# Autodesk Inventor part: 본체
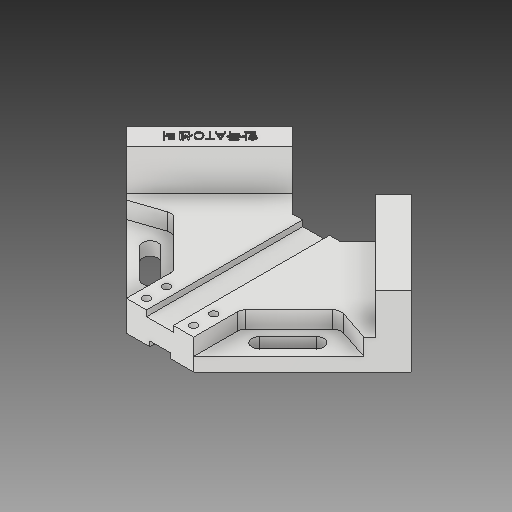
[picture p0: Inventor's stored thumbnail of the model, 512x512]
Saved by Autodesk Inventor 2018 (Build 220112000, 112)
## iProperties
Created: 2019-04
Part Number: 본체
Material: ABS Plastic
Document SubType Name: Modeling
Designer: Administrator
Density: 1.06 g/cm^3
Appearance: Smooth - White
Mass: 236.127 g
Surface Area: 426.592 cm^2
Volume: 222.762 cm^3
Author: Administrator
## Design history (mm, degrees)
sketch "Sketch2"
  geometry: L1 (84.853, -84.853)-(35.355, -134.35); L2 (-35.355, -134.35)-(-84.853, -84.853); L3 (-84.853, -84.853)-(-20, -20); L4 (20, -20)-(84.853, -84.853); L5 (84.853, -84.853)-(-84.853, -84.853); L6 (0, -169.706)-(0, 0); L7 (20, -20)-(-20, -20); L8 (35.355, -134.35)-(14.005, -113); L9 (14.005, -113)-(-14.005, -113); L10 (-14.005, -113)-(-35.355, -134.35); L11 (35.355, -134.35)-(84.853, -84.853); L12 (84.853, -84.853)-(74.246, -74.246); L13 (74.246, -74.246)-(24.749, -123.744); L14 (24.749, -123.744)-(35.355, -134.35); L15 (-35.355, -134.35)-(-84.853, -84.853); L16 (-84.853, -84.853)-(-74.246, -74.246); L17 (-74.246, -74.246)-(-24.749, -123.744); L18 (-24.749, -123.744)-(-35.355, -134.35); 2 further points
  constraints: 36 end point, 7 parallel, 5 perpendicular, 2 horizontal, 2 midpoint, 1 coincident, 1 collinear, 1 vertical, 2 other
  dimensions: "d25" = 40 distance of L4.start L3.end; "d26" = 20 distance from line of point (0, 0) L7; "d27" = 50 distance from line of L6.start L8; "d28" = 50 distance from line of L6.start L10; "d29" = 93 distance between parallel lines of L7 L9; "d30" = 120 distance from line of L3 L6.start; "d31" = 120 distance from line of point (0, 0) L1; "d34" = 15 distance between parallel lines of L1 L13; "d35" = 15 distance between parallel lines of L2 L17
extrude "Extrusion1" new body sketch "Sketch2" distance "d32" = 18; taper "d33" = 0 deg
extrude "Extrusion2" join sketch "Sketch2" distance "d36" = 42; taper "d37" = 0 deg
sketch "Sketch3"
  geometry: L1 (-20, 20)-(-84.853, 84.853) reference; L2 (-70.711, 70.711)-(-52.429, 76.805); L3 (-47.312, 75.597)-(-21.464, 49.749); L4 (-20, 46.213)-(-20, 20); L5 (-70.711, 70.711)-(-20, 20); L6 (20, 20)-(-20, 20) reference; L7 (0, 20)-(0, 113); L8 (-14.005, 113)-(14.005, 113) reference; L9 (-84.853, 84.853)-(-35.355, 134.35) reference; L10 (20, 46.213)-(20, 20); L11 (20, 20)-(70.711, 70.711); L12 (47.312, 75.597)-(21.464, 49.749); L13 (70.711, 70.711)-(52.429, 76.805); A1 r 5 centre (-50.848, 72.061) between (-47.312, 75.597) and (-52.429, 76.805); A2 r 5 centre (-25, 46.213) between (-20, 46.213) and (-21.464, 49.749); A3 r 5 centre (25, 46.213) between (21.464, 49.749) and (20, 46.213); A4 r 5 centre (50.848, 72.061) between (52.429, 76.805) and (47.312, 75.597); 6 further points
  constraints: 18 end point, 11 point on line, 8 point on circle, 8 tangent, 6 symmetric about line, 4 centre point, 3 equal radius, 2 midpoint, 1 collinear, 1 vertical
  dimensions: "d38" = 20 distance from line of L2.start L9; "d39" = 30 distance from line of point (-49.497, 77.782) L9; "d41" = 20 distance from line of L1 point (-49.497, 77.782); "d42" = 40 diameter of L4.end L7; "d49" = 20 distance from line of L5 point (-20, 48.284); "d50" = 5 radius of A1 (derived)
extrude "Extrusion3" cut sketch "Sketch3" distance "d51" = 10; taper "d52" = 0 deg
sketch "Sketch4"
  geometry: L1 (49.497, 63.64)-(32.527, 46.669); L2 (46.315, 66.822)-(29.345, 49.851); L3 (35.709, 43.487)-(52.679, 60.458); L4 (20, 20)-(-20, 20) reference; L5 (0, 20)-(0, 113); L6 (-14.005, 113)-(14.005, 113) reference; L7 (84.853, 84.853)-(20, 20) reference; L8 (35.355, 134.35)-(84.853, 84.853) reference; L9 (-35.709, 43.487)-(-52.679, 60.458); L10 (-46.315, 66.822)-(-29.345, 49.851); L11 (-49.497, 63.64)-(-32.527, 46.669); A1 r 4.5 centre (49.497, 63.64) between (52.679, 60.458) and (46.315, 66.822); A2 r 4.5 centre (32.527, 46.669) between (29.345, 49.851) and (35.709, 43.487); A3 r 4.5 centre (-49.497, 63.64) between (-46.315, 66.822) and (-52.679, 60.458); A4 r 4.5 centre (-32.527, 46.669) between (-35.709, 43.487) and (-29.345, 49.851); 2 further points
  constraints: 16 end point, 8 point on circle, 6 symmetric about line, 4 centre point, 4 tangent, 3 midpoint, 2 parallel, 1 coincident, 2 other
  dimensions: "d54" = 9 distance between parallel lines of L3 L2; "d55" = 10 distance from line of L7 point (41.012, 55.154); "d57" = 40 distance from line of L1.start L8; "d59" = 24 distance of L11.start L11.end
extrude "Extrusion4" cut sketch "Sketch4" distance "d60" = 8; taper "d61" = 0 deg
sketch "Sketch5"
  geometry: L1 (-8, 113)-(8, 113); L2 (8, 113)-(8, 20); L3 (8, 20)-(-8, 20); L4 (-8, 20)-(-8, 113); L5 (-14.005, 113)-(14.005, 113) reference; L6 (20, 20)-(-20, 20) reference; 3 further points
  constraints: 8 end point, 4 midpoint, 2 parallel, 1 horizontal, 1 perpendicular
  dimensions: "d62" = 16 distance between parallel lines of L2 L4
extrude "Extrusion5" cut sketch "Sketch5" distance "d63" = 3.5; taper "d64" = 0 deg
sketch "Sketch6"
  geometry: L1 (-6, -20)-(6, -20); L2 (6, -20)-(6, -113); L3 (6, -113)-(-6, -113); L4 (-6, -113)-(-6, -20); L5 (8, -20)-(-8, -20) reference; L6 (-8, -113)-(8, -113) reference; 3 further points
  constraints: 8 end point, 4 midpoint, 2 parallel, 1 horizontal, 1 perpendicular
  dimensions: "d65" = 12 distance between parallel lines of L2 L4
extrude "Extrusion6" cut sketch "Sketch6" distance "d66" = 3; taper "d67" = 0 deg
sketch "Sketch7"
  geometry: L1 (8, 20)-(-8, 20) reference; L2 (0, 20)-(-14, 20); L3 (-14, 20)-(-14, 26); L4 (-14, 26)-(-14, 38); L5 (0, 20)-(0, 35.802); L6 (14, 26)-(14, 38); L7 (14, 20)-(14, 26); L8 (0, 20)-(14, 20); C1 r 2.25 at (-14, 38); C2 r 2.25 at (-14, 26); C3 r 2.25 at (14, 38); C4 r 2.25 at (14, 26); C5 r 4 at (-14, 38); C6 r 4 at (-14, 26); C7 r 4 at (14, 26); C8 r 4 at (14, 38); 1 further point
  constraints: 14 end point, 8 centre point, 8 coincident, 3 symmetric about line, 2 point on line, 1 collinear, 1 midpoint, 1 perpendicular, 1 vertical
  dimensions: "d68" = 14 distance of L2.start L2.end; "d69" = 6 distance of L2.end L3.end; "d70" = 12 distance of L3.end L4.end; "d71" = 4.5 diameter of C1; "d72" = 4.5 diameter of C3; "d73" = 4.5 diameter of C4; "d74" = 4.5 diameter of C2; "d75" = 8 diameter of C5; "d76" = 8 diameter of C6; "d77" = 8 diameter of C7; "d78" = 8 diameter of C8
extrude "Extrusion7" cut sketch "Sketch7" distance "d79" = 8; taper "d80" = 0 deg
sketch "Sketch9"
  geometry: C1 r 2.25 at (0, 0) reference; C2 r 4 at (0, 0); C3 r 2.25 at (0, 12) reference; C4 r 4 at (0, 12); C5 r 2.25 at (28, 12) reference; C6 r 4 at (28, 12); C7 r 2.25 at (28, 0) reference; C8 r 4 at (28, 0); 1 further point
  constraints: 4 centre point, 4 coincident
  dimensions: "d81" = 8 diameter of C2; "d82" = 8 diameter of C4; "d83" = 8 diameter of C6; "d84" = 8 diameter of C8
extrude "Extrusion8" cut sketch "Sketch9" distance "d85" = 80; taper "d86" = 0 deg
sketch "Sketch10"
  geometry: L1 (-35.355, 134.35)-(-14.005, 113) reference; L2 (-35.355, 134.35)-(-30.052, 129.047); L3 (-30.052, 129.047)-(-54.801, 104.298); 2 further points
  constraints: 4 end point, 1 coincident, 1 perpendicular, 1 point on line, 1 other
  dimensions: "d87" = 7.5 distance of L1.start L2.end; "d88" = 35 distance of L2.end L3.end
emboss "Emboss1" sketch "Sketch10" dims "d25" = 40, "d26" = 20, "d27" = 50, "d28" = 50, "d29" = 93, "d30" = 120, "d31" = 120, "d34" = 15, "d35" = 15, "d89" = 0.5, "d90" = 0
body "Solid1"
